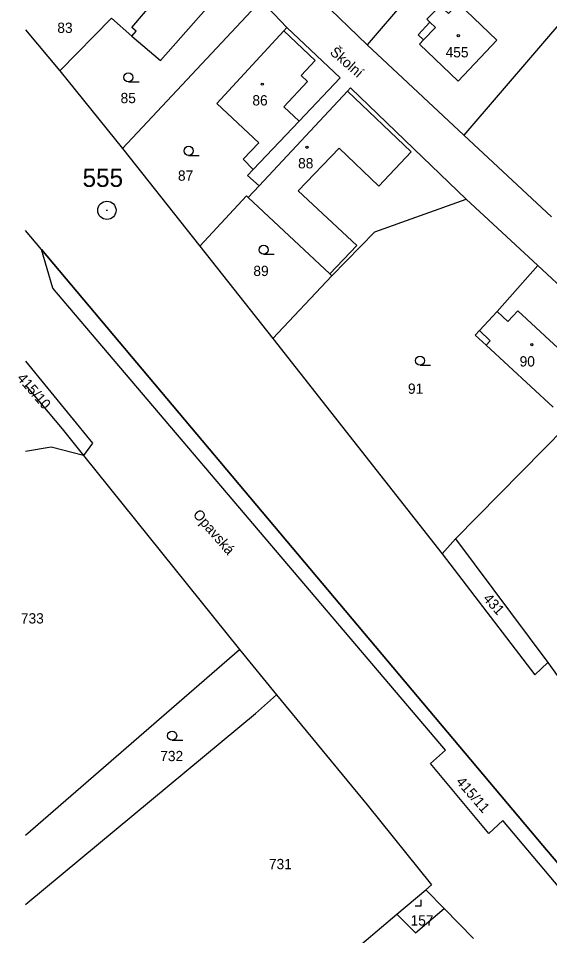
# Model space of a CAD drawing. Extents: x -504997 to -503568, y -1079870 to -1078007.
# Drawn here: x -504600.9 to -504513, y -1078780.8 to -1078629.2 of the extents above; entities that cross this region are included whole.
import ezdxf

# ---------------------------------------------------------------- set-up
doc = ezdxf.new("R2010")
doc.units = 0
for name, color, linetype in [('Hranice parcel', 7, 'Continuous'), ('Parcelní čísla', 7, 'Continuous'), ('Pop  PČ popisy', 7, 'Continuous'), ('Vnitřní kresba', 7, 'Continuous'), ('Vrstva 30', 7, 'Continuous'), ('Vrstva 31', 7, 'Continuous'), ('Vrstva 32', 7, 'Continuous'), ('Vrstva 54', 7, 'Continuous'), ('Značky budov', 7, 'Continuous'), ('Značky kultur', 7, 'Continuous')]:
    doc.layers.add(name, color=color, linetype=linetype)

msp = doc.modelspace()

# ---------------------------------------------------------------- linework, layer by layer
at = {"layer": 'Hranice parcel'}
for p, q in [((-504583.69, -1078650.73), (-504560.74, -1078626.29)), ((-504556.52, -1078630.76), (-504560.74, -1078626.29)), ((-504550.86, -1078626.15), (-504543.22, -1078633.58)), ((-504536.89, -1078626.15), (-504543.22, -1078633.58)), ((-504508.05, -1078626.15), (-504527.23, -1078648.54)), ((-504594.06, -1078637.92), (-504585.52, -1078629.17)), ((-504599.72, -1078631.15), (-504594.06, -1078637.92)), ((-504543.22, -1078633.58), (-504527.23, -1078648.54)), ((-504594.06, -1078637.92), (-504583.69, -1078650.73)), ((-504527.23, -1078648.54), (-504512.71, -1078662.02)), ((-504583.69, -1078650.73), (-504570.88, -1078666.85)), ((-504563.74, -1078652.52), (-504562.08, -1078654.23)), ((-504561.09, -1078656.9), (-504562.9, -1078658.83)), ((-504515.01, -1078670.07), (-504526.83, -1078659.1)), ((-504595.19, -1078673.8), (-504597.09, -1078667.4)), ((-504570.88, -1078666.85), (-504558.84, -1078682.13)), ((-504515.01, -1078670.07), (-504521.74, -1078677.69)), ((-504497.46, -1078686.36), (-504515.01, -1078670.07)), ((-504558.84, -1078682.13), (-504549.08, -1078671.78)), ((-504558.84, -1078682.13), (-504530.83, -1078717.69)), ((-504528.6, -1078715.23), (-504510.4, -1078696.81)), ((-504590.14, -1078701.47), (-504564.35, -1078733.55)), ((-504530.83, -1078717.69), (-504528.6, -1078715.23)), ((-504528.6, -1078715.23), (-504513.37, -1078735.66)), ((-504564.35, -1078733.55), (-504558.23, -1078741)), ((-504513.37, -1078735.66), (-504512.16, -1078737.29)), ((-504538.29, -1078777.24), (-504533.54, -1078773.23)), ((-504533.54, -1078773.23), (-504530.49, -1078776.34)), ((-504525.66, -1078781.28), (-504530.49, -1078776.34)), ((-504599.72, -1078829.02), (-504538.29, -1078777.24))]:
    msp.add_line(p, q, dxfattribs=at)
for points in [[(-504585.52, -1078629.17), (-504582.12, -1078632.17), (-504577.37, -1078636.19), (-504568.57, -1078626.15)], [(-504533.89, -1078632.8), (-504534.81, -1078631.93), (-504532.83, -1078629.85), (-504533.33, -1078629.38), (-504531.17, -1078627.13), (-504529.78, -1078628.45), (-504528.15, -1078626.72), (-504521.75, -1078632.83), (-504528.16, -1078639.59), (-504534.56, -1078633.51), (-504533.89, -1078632.8)], [(-504556.52, -1078630.76), (-504557, -1078631.27), (-504568.1, -1078643.27)], [(-504562.08, -1078654.23), (-504554.47, -1078646.21), (-504547.69, -1078639.08), (-504556.52, -1078630.76)], [(-504526.83, -1078659.1), (-504535.5, -1078650.8), (-504545.97, -1078640.71), (-504546.48, -1078641.26), (-504561.09, -1078656.9)], [(-504568.1, -1078643.27), (-504561.12, -1078649.82), (-504563.74, -1078652.52)], [(-504561.09, -1078656.9), (-504563, -1078655.2), (-504562.08, -1078654.23)], [(-504570.88, -1078666.85), (-504563.18, -1078658.57), (-504562.9, -1078658.83)], [(-504562.9, -1078658.83), (-504549.41, -1078671.47), (-504549.08, -1078671.78)], [(-504549.08, -1078671.78), (-504541.95, -1078664.49), (-504526.83, -1078659.1)], [(-504597.09, -1078667.4), (-504599.72, -1078664.27)], [(-504597.09, -1078667.4), (-504514.19, -1078765.94), (-504428.7, -1078866.55), (-504382.03, -1078924.33)], [(-504382.03, -1078926.66), (-504397.6, -1078907.92), (-504520.79, -1078761.79), (-504523.08, -1078763.96), (-504532.75, -1078752.34), (-504530.29, -1078750.16), (-504595.19, -1078673.8)], [(-504521.74, -1078677.69), (-504524.65, -1078680.82), (-504525.34, -1078681.56), (-504523.53, -1078683.23), (-504512.44, -1078693.49)], [(-504599.72, -1078685.86), (-504588.66, -1078699.42), (-504590.14, -1078701.47)], [(-504599.72, -1078689.85), (-504593.67, -1078697.08), (-504590.14, -1078701.47)], [(-504590.14, -1078701.47), (-504595.47, -1078700.11), (-504599.72, -1078700.82)], [(-504530.83, -1078717.69), (-504515.48, -1078737.7), (-504513.37, -1078735.66)], [(-504599.72, -1078764.2), (-504564.35, -1078733.55)], [(-504599.72, -1078775.67), (-504599.34, -1078775.34), (-504561.66, -1078744.08), (-504558.23, -1078741)], [(-504558.23, -1078741), (-504543.24, -1078759.21), (-504532.57, -1078772.41), (-504533.54, -1078773.23)], [(-504538.29, -1078777.24), (-504535.24, -1078780.35), (-504530.49, -1078776.34)]]:
    msp.add_lwpolyline(points, dxfattribs=at)
at = {"layer": 'Vnitřní kresba'}
for p, q in [((-504582.14, -1078630.76), (-504578.29, -1078626.15)), ((-504581.43, -1078631.35), (-504582.14, -1078630.76)), ((-504533.89, -1078632.8), (-504531.92, -1078630.72)), ((-504531.92, -1078630.72), (-504532.83, -1078629.85)), ((-504582.12, -1078632.17), (-504581.43, -1078631.35)), ((-504557, -1078631.27), (-504551.82, -1078636.18)), ((-504551.82, -1078636.18), (-504554.11, -1078638.67)), ((-504553.08, -1078639.67), (-504556.98, -1078643.85)), ((-504554.11, -1078638.67), (-504553.08, -1078639.67)), ((-504546.48, -1078641.26), (-504535.94, -1078651.28)), ((-504556.98, -1078643.85), (-504554.47, -1078646.21)), ((-504547.86, -1078650.67), (-504554.62, -1078657.74)), ((-504541.27, -1078656.98), (-504547.86, -1078650.67)), ((-504535.94, -1078651.28), (-504541.27, -1078656.98)), ((-504554.62, -1078657.74), (-504544.93, -1078666.76)), ((-504544.93, -1078666.76), (-504549.41, -1078671.47))]:
    msp.add_line(p, q, dxfattribs=at)
for points in [[(-504507.17, -1078687.86), (-504518.29, -1078677.57), (-504519.94, -1078679.35), (-504521.74, -1078677.69)], [(-504524.65, -1078680.82), (-504522.86, -1078682.51), (-504523.53, -1078683.23)]]:
    msp.add_lwpolyline(points, dxfattribs=at)
at = {"layer": 'Vrstva 30'}
msp.add_line((-504586.36, -1078660.95), (-504586.16, -1078660.95), dxfattribs=at)
msp.add_circle((-504586.26, -1078660.95), 1.51, dxfattribs=at)
at = {"layer": 'Vrstva 31'}
msp.add_line((-504586.26, -1078660.95), (-504586.26, -1078660.95), dxfattribs=at)
at = {"layer": 'Vrstva 54'}
for points in [[(-504428.7, -1078866.55), (-504514.19, -1078765.94), (-504597.09, -1078667.4)], [(-504558.84, -1078682.13), (-504530.83, -1078717.69), (-504515.48, -1078737.7), (-504513.37, -1078735.66), (-504512.16, -1078737.29), (-504507.63, -1078743.89), (-504506.21, -1078745.96), (-504510.04, -1078749.73), (-504485.94, -1078776.97), (-504483.44, -1078779.79), (-504481.39, -1078782.11), (-504435.49, -1078833.98), (-504407.21, -1078868.45)]]:
    msp.add_lwpolyline(points, dxfattribs=at)
at = {"layer": 'Značky budov'}
for centre in [(-504528.15, -1078632.08), (-504560.56, -1078640.09), (-504553.17, -1078650.53), (-504515.99, -1078683.15)]:
    msp.add_circle(centre, 0.175, dxfattribs=at)
at = {"layer": 'Značky kultur'}
for p, q in [((-504582.7, -1078639.73), (-504580.95, -1078639.73)), ((-504572.74, -1078651.87), (-504570.99, -1078651.87)), ((-504560.34, -1078668.22), (-504558.59, -1078668.22)), ((-504534.48, -1078686.54), (-504532.73, -1078686.54)), ((-504575.47, -1078748.53), (-504573.72, -1078748.53)), ((-504534.3, -1078775.9), (-504534.3, -1078774.9)), ((-504535.3, -1078775.9), (-504534.3, -1078775.9))]:
    msp.add_line(p, q, dxfattribs=at)
for centre in [(-504582.7, -1078638.98), (-504572.74, -1078651.12), (-504560.34, -1078667.47), (-504534.48, -1078685.79), (-504575.47, -1078747.78)]:
    msp.add_circle(centre, 0.75, dxfattribs=at)

# ---------------------------------------------------------------- texts
at = {"layer": 'Parcelní čísla'}
for s, p in [('83', (-504594.46, -1078631.63)), ('455', (-504530.25, -1078635.68)), ('85', (-504584, -1078643.24)), ('86', (-504562.2, -1078643.62)), ('88', (-504554.64, -1078654.02)), ('87', (-504574.51, -1078656.06)), ('89', (-504562.04, -1078671.81)), ('90', (-504518.01, -1078686.76)), ('91', (-504536.48, -1078691.27)), ('733', (-504600.49, -1078729.23)), ('732', (-504577.44, -1078751.98)), ('731', (-504559.47, -1078769.83)), ('157', (-504536.05, -1078779.15))]:
    msp.add_text(s, height=1.7, dxfattribs=at).set_placement(p)
for s, rotation, p in [('415/10', 311, (-504601.23, -1078688.75)), ('431', 312, (-504524.16, -1078725.19)), ('415/11', 311, (-504528.63, -1078755.45))]:
    msp.add_text(s, height=1.7, rotation=rotation, dxfattribs=at).set_placement(p)
at = {"layer": 'Pop  PČ popisy'}
for s, rotation, p in [('Školní', 319, (-504549.51, -1078635.02)), ('Opavská', 311, (-504572.14, -1078711.27))]:
    msp.add_text(s, height=1.7, rotation=rotation, dxfattribs=at).set_placement(p)
at = {"layer": 'Vrstva 32'}
msp.add_text('555', height=3, dxfattribs=at).set_placement((-504590.28, -1078657.08))

doc.saveas('drawing.dxf')
